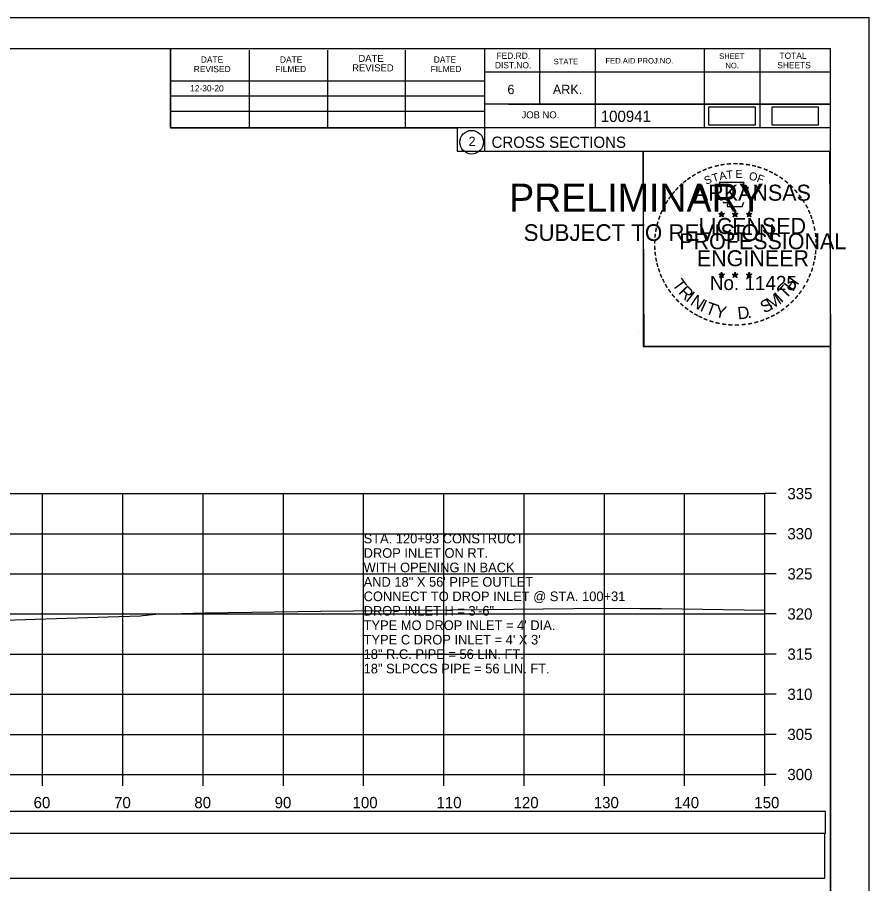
# Model space of a CAD drawing. Extents: x 1370538 to 1372872, y 376220 to 381127.
# Drawn here: x 1372098.8 to 1372204.9, y 380363.8 to 380471.7 of the extents above; entities that cross this region are included whole.
import ezdxf

# ---------------------------------------------------------------- set-up
doc = ezdxf.new("R2010")
doc.units = 0
for name, color, linetype in [('Default', 7, 'Continuous'), ('R_Border Notes', 7, 'Continuous'), ('R_Border PE', 7, 'Continuous'), ('R_Border Prem', 7, 'Continuous'), ('R_Dimension', 7, 'Continuous'), ('R_Fin Surface', 7, 'Continuous'), ('R_Grid', 7, 'Continuous'), ('R_No Plot', 7, 'Continuous'), ('R_Water Annot', 7, 'Continuous'), ('T_Detection Zones', 7, 'Continuous'), ('T_Indications', 7, 'Continuous'), ('T_Notes', 7, 'Continuous')]:
    doc.layers.add(name, color=color, linetype=linetype)

msp = doc.modelspace()

# ---------------------------------------------------------------- linework, layer by layer
at = {"layer": 'Default'}
for points in [[(1372184.96, 380458.33), (1372190.79, 380458.33), (1372190.79, 380460.51), (1372184.96, 380460.51)], [(1372192.83, 380458.33), (1372198.66, 380458.33), (1372198.66, 380460.51), (1372192.83, 380460.51)]]:
    msp.add_lwpolyline(points, close=True, dxfattribs=at)
at = {"layer": 'R_Border Notes'}
for p, q in [((1371883.97, 380467.83), (1372200.15, 380467.83)), ((1372117.89, 380457.95), (1372117.89, 380467.83)), ((1372127.75, 380457.95), (1372127.75, 380467.63)), ((1372137.51, 380457.95), (1372137.51, 380467.63)), ((1372147.19, 380457.95), (1372147.19, 380467.63)), ((1372157.05, 380467.83), (1372157.05, 380455.03)), ((1372163.89, 380467.83), (1372163.89, 380460.89)), ((1372170.83, 380467.83), (1372170.83, 380457.95)), ((1372184.41, 380467.83), (1372184.41, 380457.95)), ((1372191.35, 380467.83), (1372191.35, 380457.95)), ((1372200.15, 380262.37), (1372200.15, 380467.83)), ((1372200.15, 380464.89), (1372157.05, 380464.89)), ((1372200.15, 380464.91), (1372200.15, 380464.91)), ((1372117.89, 380463.81), (1372157.05, 380463.81)), ((1372117.89, 380461.95), (1372157.05, 380461.95)), ((1372200.15, 380460.89), (1372157.05, 380460.89)), ((1372160.01, 380460.89), (1372200.15, 380460.89)), ((1372117.89, 380457.95), (1372117.89, 380460.01)), ((1372117.89, 380460.01), (1372157.05, 380460.01)), ((1372200.15, 380457.95), (1372117.89, 380457.95)), ((1372157.05, 380455.03), (1372200.15, 380455.03))]:
    msp.add_line(p, q, dxfattribs=at)
msp.add_circle((1372155.43, 380456.16), 1.47, dxfattribs=at)
at = {"layer": 'R_Border Prem'}
for p, q in [((1372191.97, 380377.37), (1372191.97, 380412.37)), ((1372193.37, 380412.37), (1372191.97, 380412.37)), ((1372193.37, 380407.37), (1372191.97, 380407.37)), ((1372193.37, 380402.37), (1372191.97, 380402.37)), ((1372193.37, 380397.37), (1372191.97, 380397.37)), ((1372193.37, 380392.37), (1372191.97, 380392.37)), ((1372193.37, 380387.37), (1372191.97, 380387.37)), ((1372193.37, 380382.37), (1372191.97, 380382.37)), ((1371891.97, 380377.37), (1372191.97, 380377.37)), ((1372101.97, 380375.97), (1372101.97, 380377.37)), ((1372111.97, 380375.97), (1372111.97, 380377.37)), ((1372121.97, 380375.97), (1372121.97, 380377.37)), ((1372131.97, 380375.97), (1372131.97, 380377.37)), ((1372141.97, 380375.97), (1372141.97, 380377.37)), ((1372151.97, 380375.97), (1372151.97, 380377.37)), ((1372161.97, 380375.97), (1372161.97, 380377.37)), ((1372171.97, 380375.97), (1372171.97, 380377.37)), ((1372181.97, 380375.97), (1372181.97, 380377.37)), ((1372191.97, 380375.97), (1372191.97, 380377.37)), ((1372193.37, 380377.37), (1372191.97, 380377.37))]:
    msp.add_line(p, q, dxfattribs=at)
at = {"layer": 'R_Dimension'}
msp.add_lwpolyline([(1372094.59, 380396.52), (1372110.16, 380397.01), (1372114.18, 380397.14), (1372114.48, 380397.18), (1372116.1, 380397.35), (1372118.49, 380397.4), (1372119.3, 380397.43), (1372122.23, 380397.53), (1372136.65, 380397.72), (1372156.88, 380397.95), (1372168.08, 380398.07), (1372169.69, 380398.1), (1372176.39, 380398.06), (1372179.1, 380398.05), (1372191.97, 380397.83)], dxfattribs=at)
at = {"layer": 'R_Fin Surface'}
msp.add_lwpolyline([(1371884.44, 380364.44), (1372199.45, 380364.44), (1372199.45, 380370), (1371884.44, 380370)], close=True, dxfattribs=at)
at = {"layer": 'R_Grid'}
for p, q in [((1371891.97, 380412.37), (1372191.97, 380412.37)), ((1372101.97, 380377.37), (1372101.97, 380412.37)), ((1372111.97, 380377.37), (1372111.97, 380412.37)), ((1372121.97, 380377.37), (1372121.97, 380412.37)), ((1372131.97, 380377.37), (1372131.97, 380412.37)), ((1372141.97, 380377.37), (1372141.97, 380412.37)), ((1372151.97, 380377.37), (1372151.97, 380412.37)), ((1372161.97, 380377.37), (1372161.97, 380412.37)), ((1372171.97, 380377.37), (1372171.97, 380412.37)), ((1372181.97, 380377.37), (1372181.97, 380412.37)), ((1372191.97, 380377.37), (1372191.97, 380412.37)), ((1371891.97, 380407.37), (1372191.97, 380407.37)), ((1371891.97, 380402.37), (1372191.97, 380402.37)), ((1371891.97, 380397.37), (1372191.97, 380397.37)), ((1371891.97, 380392.37), (1372191.97, 380392.37)), ((1371891.97, 380387.37), (1372191.97, 380387.37)), ((1371891.97, 380382.37), (1372191.97, 380382.37)), ((1371891.97, 380377.37), (1372191.97, 380377.37))]:
    msp.add_line(p, q, dxfattribs=at)
at = {"layer": 'R_No Plot'}
for p, q in [((1371871.57, 380471.72), (1372204.9, 380471.72)), ((1372176.18, 380432.57), (1372176.18, 380432.57))]:
    msp.add_line(p, q, dxfattribs=at)
for points in [[(1371871.56, 380471.72), (1372204.9, 380471.72), (1372204.9, 380258.39), (1371871.56, 380258.39)], [(1372117.89, 380467.83), (1372117.89, 380457.95), (1372153.62, 380457.95), (1372153.62, 380455.03), (1372176.82, 380455.03), (1372176.82, 380430.7), (1372200.15, 380430.7), (1372200.15, 380262.37), (1371883.97, 380262.37), (1371883.97, 380467.83)], [(1372176.82, 380455.03), (1372200.03, 380455.03), (1372200.15, 380430.7), (1372176.94, 380430.7)]]:
    msp.add_lwpolyline(points, close=True, dxfattribs=at)
at = {"layer": 'T_Detection Zones'}
msp.add_lwpolyline([(1371884.38, 380370.06), (1372199.5, 380370.06), (1372199.5, 380372.77), (1371884.38, 380372.77)], close=True, dxfattribs=at)
at = {"layer": 'T_Indications'}
for p, q in [((1372186.23, 380447.28), (1372186.58, 380447.17)), ((1372186.23, 380447.28), (1372186.48, 380447.24)), ((1372186.23, 380447.28), (1372186.47, 380447.16)), ((1372186.36, 380446.88), (1372186.58, 380447.17)), ((1372186.36, 380446.88), (1372186.49, 380447.12)), ((1372186.36, 380446.88), (1372186.58, 380447.09)), ((1372186.58, 380447.54), (1372186.54, 380447.29)), ((1372186.58, 380447.17), (1372186.58, 380447.54)), ((1372186.58, 380447.54), (1372186.63, 380447.29)), ((1372186.93, 380447.28), (1372186.58, 380447.17)), ((1372186.79, 380446.88), (1372186.58, 380447.17)), ((1372186.79, 380446.88), (1372186.58, 380447.09)), ((1372186.93, 380447.28), (1372186.64, 380447.23)), ((1372186.79, 380446.88), (1372186.66, 380447.17)), ((1372186.93, 380447.28), (1372186.72, 380447.18)), ((1372187.9, 380447.28), (1372188.25, 380447.17)), ((1372187.9, 380447.28), (1372188.15, 380447.24)), ((1372187.9, 380447.28), (1372188.14, 380447.16)), ((1372188.03, 380446.88), (1372188.25, 380447.17)), ((1372188.03, 380446.88), (1372188.16, 380447.12)), ((1372188.03, 380446.88), (1372188.25, 380447.09)), ((1372188.25, 380447.54), (1372188.21, 380447.29)), ((1372188.25, 380447.17), (1372188.25, 380447.54)), ((1372188.25, 380447.54), (1372188.3, 380447.29)), ((1372188.6, 380447.28), (1372188.25, 380447.17)), ((1372188.46, 380446.88), (1372188.25, 380447.17)), ((1372188.46, 380446.88), (1372188.25, 380447.09)), ((1372188.6, 380447.28), (1372188.31, 380447.23)), ((1372188.46, 380446.88), (1372188.33, 380447.17)), ((1372188.6, 380447.28), (1372188.39, 380447.18)), ((1372189.67, 380447.27), (1372190.01, 380447.16)), ((1372189.67, 380447.27), (1372189.92, 380447.23)), ((1372189.67, 380447.27), (1372189.9, 380447.15)), ((1372189.8, 380446.86), (1372190.01, 380447.16)), ((1372189.8, 380446.86), (1372189.92, 380447.11)), ((1372189.8, 380446.86), (1372190.01, 380447.08)), ((1372190.01, 380447.53), (1372189.97, 380447.27)), ((1372190.01, 380447.16), (1372190.01, 380447.53)), ((1372190.01, 380447.53), (1372190.06, 380447.28)), ((1372190.36, 380447.27), (1372190.01, 380447.16)), ((1372190.23, 380446.86), (1372190.01, 380447.16)), ((1372190.23, 380446.86), (1372190.01, 380447.08)), ((1372190.36, 380447.27), (1372190.08, 380447.22)), ((1372190.23, 380446.86), (1372190.09, 380447.15)), ((1372190.36, 380447.27), (1372190.16, 380447.17)), ((1372186.23, 380439.71), (1372186.58, 380439.6)), ((1372186.23, 380439.71), (1372186.48, 380439.67)), ((1372186.23, 380439.71), (1372186.46, 380439.59)), ((1372186.36, 380439.3), (1372186.58, 380439.6)), ((1372186.36, 380439.3), (1372186.49, 380439.55)), ((1372186.36, 380439.3), (1372186.57, 380439.52)), ((1372186.58, 380439.96), (1372186.54, 380439.71)), ((1372186.79, 380439.3), (1372186.57, 380439.52)), ((1372186.58, 380439.6), (1372186.58, 380439.96)), ((1372186.58, 380439.96), (1372186.63, 380439.71)), ((1372186.92, 380439.71), (1372186.58, 380439.6)), ((1372186.79, 380439.3), (1372186.58, 380439.6)), ((1372186.92, 380439.71), (1372186.64, 380439.66)), ((1372186.79, 380439.3), (1372186.65, 380439.59)), ((1372186.92, 380439.71), (1372186.72, 380439.61)), ((1372187.9, 380439.71), (1372188.25, 380439.6)), ((1372187.9, 380439.71), (1372188.15, 380439.67)), ((1372187.9, 380439.71), (1372188.13, 380439.59)), ((1372188.03, 380439.3), (1372188.25, 380439.6)), ((1372188.03, 380439.3), (1372188.16, 380439.55)), ((1372188.03, 380439.3), (1372188.24, 380439.52)), ((1372188.25, 380439.96), (1372188.2, 380439.71)), ((1372188.46, 380439.3), (1372188.24, 380439.52)), ((1372188.25, 380439.6), (1372188.25, 380439.96)), ((1372188.25, 380439.96), (1372188.29, 380439.71)), ((1372188.59, 380439.71), (1372188.25, 380439.6)), ((1372188.46, 380439.3), (1372188.25, 380439.6)), ((1372188.59, 380439.71), (1372188.31, 380439.66)), ((1372188.46, 380439.3), (1372188.32, 380439.59)), ((1372188.59, 380439.71), (1372188.39, 380439.61)), ((1372189.66, 380439.7), (1372190.01, 380439.59)), ((1372189.66, 380439.7), (1372189.92, 380439.66)), ((1372189.66, 380439.7), (1372189.9, 380439.58)), ((1372189.8, 380439.29), (1372190.01, 380439.59)), ((1372189.8, 380439.29), (1372189.92, 380439.54)), ((1372189.8, 380439.29), (1372190.01, 380439.51)), ((1372190.01, 380439.95), (1372189.97, 380439.7)), ((1372190.01, 380439.59), (1372190.01, 380439.95)), ((1372190.01, 380439.95), (1372190.06, 380439.7)), ((1372190.36, 380439.7), (1372190.01, 380439.59)), ((1372190.23, 380439.29), (1372190.01, 380439.59)), ((1372190.23, 380439.29), (1372190.01, 380439.51)), ((1372190.36, 380439.7), (1372190.07, 380439.65)), ((1372190.23, 380439.29), (1372190.09, 380439.58)), ((1372190.36, 380439.7), (1372190.16, 380439.6))]:
    msp.add_line(p, q, dxfattribs=at)
for points in [[(1372186.27, 380451.16), (1372186.54, 380450.33)], [(1372189.78, 380450.24), (1372189.93, 380450.52), (1372189.24, 380450.5), (1372189.39, 380451.16), (1372186.27, 380451.16)], [(1372186.76, 380448.74), (1372186.76, 380448.65), (1372187.33, 380448.63), (1372187.27, 380448.16), (1372189.14, 380448.16), (1372189.34, 380448.7)], [(1372186.58, 380447.54), (1372186.79, 380446.88), (1372186.23, 380447.28), (1372186.93, 380447.28), (1372186.36, 380446.88), (1372186.58, 380447.54)], [(1372188.25, 380447.54), (1372188.46, 380446.88), (1372187.9, 380447.28), (1372188.6, 380447.28), (1372188.03, 380446.88), (1372188.25, 380447.54)], [(1372190.01, 380447.53), (1372190.23, 380446.86), (1372189.67, 380447.27), (1372190.36, 380447.27), (1372189.8, 380446.86), (1372190.01, 380447.53)], [(1372186.58, 380439.96), (1372186.79, 380439.3), (1372186.23, 380439.71), (1372186.92, 380439.71), (1372186.36, 380439.3), (1372186.58, 380439.96)], [(1372188.25, 380439.96), (1372188.46, 380439.3), (1372187.9, 380439.71), (1372188.59, 380439.71), (1372188.03, 380439.3), (1372188.25, 380439.96)], [(1372190.01, 380439.95), (1372190.23, 380439.29), (1372189.66, 380439.7), (1372190.36, 380439.7), (1372189.8, 380439.29), (1372190.01, 380439.95)]]:
    msp.add_lwpolyline(points, dxfattribs=at)
for centre, radius in [((1372186.58, 380447.17), 0.172), ((1372186.58, 380447.17), 0.145), ((1372186.58, 380447.17), 0.116), ((1372186.58, 380447.17), 0.0991), ((1372186.58, 380447.17), 0.0747), ((1372186.58, 380447.17), 0.0495), ((1372186.58, 380447.17), 0.0296), ((1372188.25, 380447.17), 0.172), ((1372188.25, 380447.17), 0.145), ((1372188.25, 380447.17), 0.116), ((1372188.25, 380447.17), 0.0991), ((1372188.25, 380447.17), 0.0747), ((1372188.25, 380447.17), 0.0495), ((1372188.25, 380447.17), 0.0296), ((1372190.01, 380447.16), 0.172), ((1372190.01, 380447.16), 0.145), ((1372190.01, 380447.16), 0.116), ((1372190.01, 380447.16), 0.0991), ((1372190.01, 380447.16), 0.0747), ((1372190.01, 380447.16), 0.0495), ((1372190.01, 380447.16), 0.0296), ((1372186.58, 380439.6), 0.172), ((1372186.58, 380439.6), 0.145), ((1372186.58, 380439.6), 0.116), ((1372186.58, 380439.6), 0.0991), ((1372186.58, 380439.6), 0.0747), ((1372186.58, 380439.6), 0.0495), ((1372186.58, 380439.6), 0.0296), ((1372188.24, 380439.6), 0.172), ((1372188.24, 380439.6), 0.145), ((1372188.24, 380439.6), 0.116), ((1372188.24, 380439.6), 0.0991), ((1372188.24, 380439.6), 0.0747), ((1372188.24, 380439.6), 0.0495), ((1372188.24, 380439.6), 0.0296), ((1372190.01, 380439.59), 0.172), ((1372190.01, 380439.59), 0.145), ((1372190.01, 380439.59), 0.116), ((1372190.01, 380439.59), 0.0991), ((1372190.01, 380439.59), 0.0747), ((1372190.01, 380439.59), 0.0495), ((1372190.01, 380439.59), 0.0296)]:
    msp.add_circle(centre, radius, dxfattribs=at)

# ---------------------------------------------------------------- texts
at = {"layer": 'R_Border Notes'}
for s, height, p in [('DATE', 0.782, (1372121.69, 380466.07)), ('DATE', 0.782, (1372131.55, 380466.07)), ('DATE', 0.879, (1372141.33, 380466.17)), ('DATE', 0.782, (1372150.71, 380466.07)), ('FED.RD.', 0.782, (1372158.53, 380466.55)), ('STATE', 0.684, (1372165.65, 380465.87)), ('FED.AID PROJ.NO.', 0.684, (1372172.11, 380465.97)), ('SHEET', 0.684, (1372186.27, 380466.55)), ('TOTAL', 0.782, (1372193.79, 380466.55)), ('REVISED', 0.782, (1372120.81, 380464.89)), ('FILMED', 0.782, (1372130.97, 380464.89)), ('REVISED', 0.879, (1372140.55, 380464.99)), ('FILMED', 0.782, (1372150.31, 380464.89)), ('DIST.NO.', 0.782, (1372158.33, 380465.37)), ('NO.', 0.684, (1372187.05, 380465.37)), ('SHEETS', 0.782, (1372193.51, 380465.37)), ('6', 1.17, (1372159.89, 380462.15)), ('ARK.', 1.172, (1372165.55, 380462.15)), ('JOB NO.', 0.879, (1372161.65, 380459.13)), ('100941', 1.4, (1372171.52, 380458.69)), ('2', 1.17, (1372155.05, 380455.68)), ('CROSS SECTIONS', 1.4, (1372157.91, 380455.46))]:
    msp.add_text(s, height=height, rotation=360, dxfattribs=at).set_placement(p)
msp.add_text('12-30-20', height=0.78, dxfattribs=at).set_placement((1372120.36, 380462.49))
at = {"layer": 'R_Border PE'}
for s, p in [('335', (1372194.77, 380411.67)), ('330', (1372194.77, 380406.67)), ('325', (1372194.77, 380401.67)), ('320', (1372194.77, 380396.67)), ('315', (1372194.77, 380391.67)), ('310', (1372194.77, 380386.67)), ('305', (1372194.77, 380381.67)), ('300', (1372194.77, 380376.67)), ('60', (1372100.85, 380373.17)), ('70', (1372110.88, 380373.17)), ('80', (1372120.88, 380373.17)), ('90', (1372130.88, 380373.17)), ('100', (1372140.59, 380373.17)), ('110', (1372151.05, 380373.17)), ('120', (1372160.65, 380373.17)), ('130', (1372170.65, 380373.17)), ('140', (1372180.65, 380373.17)), ('150', (1372190.65, 380373.17))]:
    msp.add_text(s, height=1.4, dxfattribs=at).set_placement(p)
at = {"layer": 'R_Water Annot'}
for s, p in [('STA. 120+93 CONSTRUCT', (1372141.97, 380406.17)), ('DROP INLET ON RT.', (1372141.97, 380404.37)), ('WITH OPENING IN BACK', (1372141.97, 380402.57)), ('AND 18" X 56\' PIPE OUTLET', (1372141.97, 380400.77)), ('CONNECT TO DROP INLET @ STA. 100+31', (1372141.97, 380398.97)), ('DROP INLET H = 3\'-6"', (1372141.97, 380397.17)), ("TYPE MO DROP INLET = 4' DIA.", (1372141.97, 380395.37)), ("TYPE C DROP INLET = 4' X 3'", (1372141.97, 380393.57)), ('18" R.C. PIPE = 56 LIN. FT.', (1372141.97, 380391.77)), ('18" SLPCCS PIPE = 56 LIN. FT.', (1372141.97, 380389.97))]:
    msp.add_text(s, height=1.2, dxfattribs=at).set_placement(p)
at = {"layer": 'T_Indications'}
for s, height, rotation, p in [('-', 1.6, 5.8968, (1372187.18, 380452.8)), ('-', 1.6, 0.1862, (1372187.95, 380452.87)), ('-', 1.6, 357.743, (1372188.67, 380452.86)), ('-', 1.6, 28.7918, (1372183.75, 380451.7)), ('-', 1.6, 24.3072, (1372184.39, 380452.02)), ('-', 1.6, 19.1761, (1372185.02, 380452.29)), ('-', 1.6, 13.6301, (1372185.77, 380452.53)), ('A', 1, 11.2132, (1372186.37, 380451.42)), ('-', 1.6, 10.2193, (1372186.45, 380452.69)), ('T', 1, 6.0228, (1372187.22, 380451.59)), ('E', 1, 0.8323, (1372188.32, 380451.7)), ('-', 1.6, 352.1617, (1372189.42, 380452.8)), ('-', 1.6, 347.2049, (1372190.14, 380452.69)), ('-', 1.6, 342.3362, (1372190.77, 380452.54)), ('-', 1.6, 337.8551, (1372191.51, 380452.31)), ('-', 1.6, 334.1211, (1372192.14, 380452.04)), ('-', 1.6, 38.9507, (1372182.1, 380450.56)), ('-', 1.6, 36.2317, (1372182.58, 380450.94)), ('-', 1.6, 34.0636, (1372183.16, 380451.33)), ('S', 1, 21.594, (1372184.63, 380450.84)), ('T', 1, 16.4036, (1372185.54, 380451.17)), ('O', 1, 350.4515, (1372189.93, 380451.49)), ('F', 1, 340.0707, (1372190.88, 380451.26)), ('-', 1.6, 329.6409, (1372192.72, 380451.76)), ('-', 1.6, 325.8627, (1372193.36, 380451.4)), ('-', 1.6, 320.5297, (1372193.97, 380450.97)), ('-', 1.6, 48.423, (1372181.22, 380449.66)), ('-', 1.6, 42.9622, (1372181.67, 380450.14)), ('ARKANSAS', 2, 360, (1372183.13, 380448.87)), ('-', 1.6, 315.5786, (1372194.57, 380450.48)), ('-', 1.6, 309.8797, (1372195.14, 380449.93)), ('-', 1.6, 54.2325, (1372180.41, 380448.61)), ('-', 1.6, 50.6142, (1372180.82, 380449.18)), ('-', 1.6, 306.6522, (1372195.66, 380449.33)), ('-', 1.6, 62.8713, (1372179.77, 380447.47)), ('-', 1.6, 58.0706, (1372180.08, 380448.08)), ('-', 1.4, 303.6753, (1372196.15, 380448.76)), ('-', 1.6, 299.6684, (1372196.47, 380448.16)), ('-', 1.6, 67.7743, (1372179.51, 380446.86)), ('DWB', 0.01, 360, (1372186.57, 380447.17)), ('DWB', 0.01, 360, (1372188.24, 380447.17)), ('DWB', 0.01, 360, (1372190, 380447.16)), ('-', 1.6, 294.6628, (1372196.79, 380447.54)), ('-', 1.6, 290.5728, (1372197.05, 380446.97)), ('-', 1.6, 75.461, (1372179.09, 380445.52)), ('-', 1.6, 72.3945, (1372179.29, 380446.23)), ('LICENSED', 2, 360, (1372183.72, 380444.72)), ('-', 1.6, 285.1233, (1372197.28, 380446.39)), ('-', 1.6, 81.2013, (1372178.96, 380444.8)), ('-', 1.6, 280.5493, (1372197.48, 380445.65)), ('-', 1.6, 89.0622, (1372178.86, 380443.41)), ('-', 1.6, 85.1863, (1372178.88, 380444.11)), ('PROFESSIONAL', 2, 360, (1372181.3, 380442.82)), ('-', 1.6, 276.5962, (1372197.64, 380444.88)), ('-', 1.6, 274.3301, (1372197.7, 380444.16)), ('-', 1.6, 94.1959, (1372178.89, 380442.69)), ('-', 1.6, 269.9407, (1372197.74, 380443.52)), ('-', 1.6, 98.9479, (1372178.97, 380442.02)), ('-', 1.6, 101.7149, (1372179.1, 380441.29)), ('ENGINEER', 2, 360, (1372183.49, 380440.7)), ('-', 1.6, 260.9953, (1372197.65, 380442.2)), ('-', 1.6, 263.5172, (1372197.72, 380442.86)), ('-', 1.6, 105.4578, (1372179.26, 380440.69)), ('-', 1.6, 255.7626, (1372197.54, 380441.53)), ('-', 1.6, 109.0874, (1372179.48, 380440.06)), ('-', 1.6, 114.0643, (1372179.73, 380439.46)), ('No. 11425', 1.757, 360, (1372185.11, 380437.74)), ('DWB', 0.01, 360, (1372186.56, 380439.59)), ('DWB', 0.01, 360, (1372188.23, 380439.6)), ('DWB', 0.01, 360, (1372190, 380439.59)), ('-', 1.6, 247.8887, (1372197.13, 380440.13)), ('-', 1.6, 252.8681, (1372197.36, 380440.81)), ('-', 1.6, 115.7289, (1372180.04, 380438.85)), ('-', 1.6, 120.4471, (1372180.39, 380438.26)), ('T', 1.54, 306.0406, (1372180.34, 380438.44)), ('T', 1.54, 46.6444, (1372194.57, 380436.53)), ('H', 1.54, 54.6088, (1372195.46, 380437.47)), ('-', 1.6, 244.6197, (1372196.87, 380439.5)), ('-', 1.6, 125.8934, (1372180.8, 380437.7)), ('R', 1.54, 314.005, (1372181.1, 380437.39)), ('I', 1.54, 321.9694, (1372182, 380436.46)), ('I', 1.54, 42.1136, (1372194, 380436.05)), ('-', 1.6, 233.8452, (1372196.08, 380438.1)), ('-', 1.6, 239.0712, (1372196.48, 380438.75)), ('-', 1.6, 130.7181, (1372181.26, 380437.15)), ('-', 1.6, 134.2238, (1372181.78, 380436.6)), ('N', 1.54, 326.5002, (1372182.57, 380435.99)), ('I', 1.54, 335.3603, (1372183.77, 380435.2)), ('T', 1.54, 339.8912, (1372184.44, 380434.87)), ('S', 1.54, 26.9312, (1372191.88, 380434.8)), ('M', 1.54, 32.6563, (1372192.72, 380435.21)), ('-', 1.6, 225.7653, (1372195.17, 380436.97)), ('-', 1.6, 231.2538, (1372195.65, 380437.53)), ('-', 1.6, 138.9338, (1372182.3, 380436.14)), ('-', 1.6, 144.6463, (1372182.86, 380435.73)), ('-', 1.6, 148.0898, (1372183.42, 380435.36)), ('Y', 1.54, 347.8556, (1372185.65, 380434.43)), ('D', 1.54, 6.3969, (1372188.64, 380434.07)), ('-', 1.6, 215.7363, (1372194.1, 380435.99)), ('-', 1.6, 221.0851, (1372194.64, 380436.46)), ('-', 1.6, 151.5704, (1372184, 380435.04)), ('-', 1.6, 154.6002, (1372184.52, 380434.79)), ('-', 1.6, 158.5612, (1372185.14, 380434.53)), ('.', 1.54, 13.7642, (1372189.83, 380434.2)), ('-', 1.6, 200.7184, (1372191.76, 380434.66)), ('-', 1.6, 204.2516, (1372192.38, 380434.94)), ('-', 1.6, 207.3568, (1372193, 380435.25)), ('-', 1.6, 212.2491, (1372193.56, 380435.6)), ('-', 1.6, 162.7983, (1372185.83, 380434.32)), ('-', 1.6, 167.5555, (1372186.55, 380434.16)), ('-', 1.6, 173.1155, (1372187.32, 380434.05)), ('-', 1.6, 176.5183, (1372188.07, 380433.99)), ('-', 1.6, 181.5918, (1372188.81, 380434.01)), ('-', 1.6, 185.8167, (1372189.62, 380434.09)), ('-', 1.6, 191.2858, (1372190.35, 380434.22)), ('-', 1.6, 195.4743, (1372191.08, 380434.42))]:
    msp.add_text(s, height=height, rotation=rotation, dxfattribs=at).set_placement(p)
at = {"layer": 'T_Notes'}
for s, height, p in [('PRELIMINARY', 3.5, (1372160.1, 380447.49)), ('DWB', 0.01, (1372160.84, 380449.34)), ('SUBJECT TO REVISION', 2.0751, (1372161.91, 380443.86))]:
    msp.add_text(s, height=height, rotation=360, dxfattribs=at).set_placement(p)

doc.saveas('drawing.dxf')
